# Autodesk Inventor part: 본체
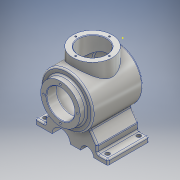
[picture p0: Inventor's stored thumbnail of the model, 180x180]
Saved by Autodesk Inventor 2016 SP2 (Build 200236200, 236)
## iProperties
Created: 2018-08
Part Number: 본체
Material: 알루미늄 6061
Document SubType Name: Modeling
Designer: Administrator
Density: 2.7 g/cm^3
Appearance: 알루미늄 - 평지
Mass: 1907.47 g
Surface Area: 1089.79 cm^2
Volume: 706.47 cm^3
Author: Administrator
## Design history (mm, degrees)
sketch "스케치3"
  geometry: L1 (-108, 50)-(-11.329, 50); L2 (-108, 50)-(-108, 0); L3 (0, 50)-(0, 0); L4 (-108, 0)-(0, 0); L5 (-108, 0)-(0, 0); A1 r 116 centre (-116, 0) between (0, 0) and (-11.329, 50); 1 further point
  constraints: 10 end point, 2 horizontal, 2 point on circle, 2 vertical, 1 centre point, 1 coincident, 1 collinear, 1 point on line
  dimensions: "d6" = 100 diameter of L1 L4; "d7" = 108 distance of L1.start L3.start; "d8" = 116 radius of A1
revolve "회전2" sketch "스케치3" stored, may be unused: angle "d9" = 90 deg
sketch "스케치4"
  geometry: C1 r 38 at (0, 0); 1 further point
  constraints: 1 centre point, 1 coincident
  dimensions: "d10" = 76 diameter of C1
extrude "돌출2" join sketch "스케치4" distance "d11" = 12; taper "d12" = 0 deg
node "작업 평면1"
sketch "스케치5"
  geometry: 1 further point
sketch "스케치6"
  geometry: L1 (-58, 65)-(-20, 65); L2 (-20, 65)-(-20, 17.26); L3 (-20, 17.26)-(-58, 17.26); L4 (-58, 17.26)-(-58, 65); L5 (-108, -50)-(-108, 50) reference; 1 further point
  constraints: 8 end point, 2 parallel, 1 horizontal, 1 perpendicular
  dimensions: "d14" = 65 distance from line of point (0, 0) L1; "d15" = 38 distance of L1.start L1.end; "d16" = 50 distance between parallel lines of L5 L4
revolve "회전3" sketch "스케치6" stored, may be unused: angle "d17" = 90 deg
sketch "스케치7"
  geometry: A1 r 32.5 centre (0, 0) between (0, 32.5) and (32.5, 0); 3 further points
  constraints: 4 point on circle, 1 centre point, 1 coincident
  dimensions: "d18" = 65 diameter of A1
hole "구멍1" sketch "스케치7" at (0, 32.5), (32.5, 0), (0, -32.5), (-32.5, 0) diameter "d19" = 3.242; stored, may be unused: countersink angle "d23" = 90 deg, drill point angle "d25" = 118 deg; dims "d20" = 8, "d21" = 4, "d22" = 2, "d24" = 11.8
sketch "스케치8"
  geometry: C1 r 38 at (0, -58) reference; C2 r 27 at (0, -58); 1 further point
  constraints: 1 centre point, 1 coincident
  dimensions: "d26" = 54 diameter of C2
extrude "돌출3" cut sketch "스케치8" stored distance "d27" = 12; taper "d28" = 0 deg
sketch "스케치9"
  geometry: L1 (-96, 65)-(-96, 50) reference; L2 (-108, 50)-(-11.329, 50) reference; L3 (-20, 65)-(-20, 50) reference; L4 (-120, 38)-(-120, -38) reference; L5 (-108, 38)-(-120, 38) reference; L6 (-108, -50)-(-108, 50) reference; L7 (-17.837, 40)-(-98, 40); L8 (-98, 40)-(-98, 0); L9 (-98, 0)-(-10, 0); L10 (-101.3, 0)-(31.477, 0); A1 r 116 centre (-116, 0) between (-11.329, -50) and (-11.329, 50) reference; A2 r 106 centre (-116, 0) between (-10, 0) and (-17.837, 40); 1 further point
  constraints: 8 end point, 2 horizontal, 2 point on circle, 1 centre point
  dimensions: "d29" = 10 distance between parallel lines of L2 L7; "d30" = 10 radial gap between concentric circles of A1 A2
revolve "회전4" sketch "스케치9" stored, may be unused: angle "d31" = 90 deg
sketch "스케치10"
  geometry: C1 r 27 at (0, 0); 1 further point
  constraints: 1 centre point, 1 coincident
  dimensions: "d32" = 54 diameter of C1
extrude "돌출4" cut sketch "스케치10" distance "d33" = 50; taper "d34" = 0 deg
sketch "스케치11"
  geometry: A1 r 32.5 centre (0, 0) between (-32.5, 0) and (0, 32.5); 3 further points
  constraints: 4 point on circle, 1 centre point
  dimensions: "d35" = 65 diameter of A1
hole "구멍2" sketch "스케치11" at (-32.5, 0), (0, 32.5), (32.5, 0), (0, -32.5) diameter "d36" = 3.242; stored, may be unused: countersink angle "d40" = 90 deg, drill point angle "d42" = 118 deg; dims "d37" = 8, "d38" = 4, "d39" = 2, "d41" = 10
node "작업 평면3"
  node "작업 평면2"
node "작업 평면4"
node "작업 평면6"
  node "작업 평면5"
node "작업 평면7"
node "작업 평면8"
sketch "스케치13"
  geometry: L1 (-32.416, -79.198)-(-47.039, -100.082); L2 (-47.039, -100.082)-(-47.039, -113.13); L3 (-47.039, -113.13)-(-67.039, -113.13); L4 (-67.039, -113.13)-(-67.039, -123.13); L5 (-67.039, -123.13)-(-40, -123.13); L6 (-15, -123.13)-(5, -123.13); L7 (40, -123.13)-(72.961, -123.13); L8 (72.961, -123.13)-(72.961, -113.13); L9 (72.961, -113.13)-(52.961, -113.13); L10 (52.961, -113.13)-(52.961, -101.151); L11 (52.961, -101.151)-(35.552, -76.288); A1 r 50 centre (0, -41.13) between (-32.416, -79.198) and (35.552, -76.288) reference; A2 r 12.5 centre (-27.5, -123.13) between (-15, -123.13) and (-40, -123.13); A3 r 17.5 centre (22.5, -123.13) between (40, -123.13) and (5, -123.13); 1 further point
  constraints: 22 end point, 6 perpendicular, 6 point on circle, 2 centre point, 2 horizontal, 1 vertical
  dimensions: "d54" = 20 distance of L8.end L9.end; "d55" = 20 distance of L2.end L3.end; "d58" = 82 distance from line of L7 point (0, -41.13); "d59" = 72 vertical distance of point (0, -41.13) L8.end; "d60" = 82 distance from line of point (0, -41.13) L5; "d61" = 72 distance from line of point (0, -41.13) L3; "d62" = 82 distance from line of point (0, -41.13) L6; "d63" = 35 deg angle of L4 L1; "d64" = 35 deg angle of L8 L11; "d65" = 25 diameter of A2; "d66" = 35 diameter of A3; "d67" = 27.5 horizontal distance of point (0, -41.13) A2.centre; "d68" = 22.5 horizontal distance of point (0, -41.13) A3.centre; "d69" = 140 distance of L7.end L4.end; "d93" = 10 distance of L7.end L8.end (derived)
extrude "돌출5" join sketch "스케치13" distance "d70" = 80; taper "d71" = 0 deg
sketch "스케치14"
  geometry: 1 further point
fillet "모깎기1" dims "d72" = 3
chamfer "모따기1" distance "d73" = 1; stored, may be unused: second distance "d74" = 2, angle "d75" = 45 deg
chamfer "모따기2" distance "d76" = 1; stored, may be unused: second distance "d77" = 2, angle "d78" = 45 deg
sketch "스케치16"
  geometry: 1 further point
fillet "모깎기2" dims "d79" = 3
fillet "모깎기3" dims "d80" = 3
fillet "모깎기4" dims "d81" = 3
sketch "스케치17"
  geometry: L1 (7, 67)-(127, 67); L2 (127, 67)-(127, 7); L3 (127, 7)-(7, 7); L4 (7, 7)-(7, 67); L5 (137, 0)-(137, 74) reference; L6 (134, 77)-(120, 77) reference; L7 (120, -3)-(134, -3) reference; L8 (-3, 74)-(-3, 0) reference; 5 further points
  constraints: 8 end point, 4 coincident, 2 parallel, 1 horizontal, 1 perpendicular
  dimensions: "d82" = 10 distance between parallel lines of L5 L2; "d83" = 10 distance between parallel lines of L6 L1; "d84" = 10 distance between parallel lines of L7 L3; "d85" = 10 distance between parallel lines of L8 L4
hole "구멍3" sketch "스케치17" at (7, 67), (7, 7), (127, 7), (127, 67) diameter "d86" = 8; stored, may be unused: countersink angle "d90" = 90 deg, drill point angle "d92" = 118 deg; dims "d87" = 8, "d88" = 4, "d89" = 2, "d91" = 10
node "솔리드2"
other parameters: "d43" = 0, "d44" = -147
